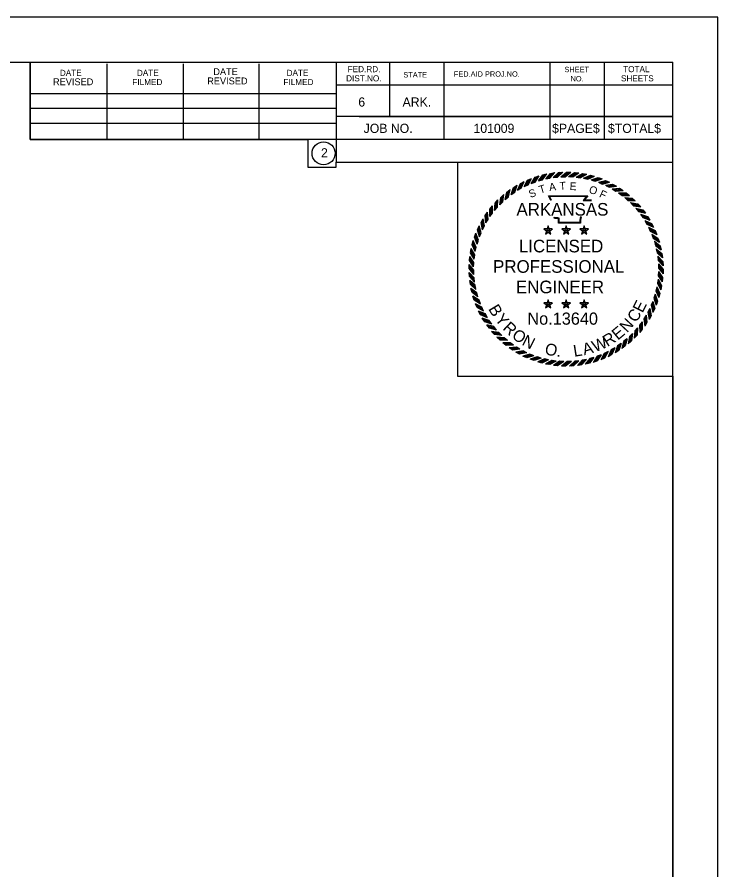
# Model space of a CAD drawing. Extents: x 0 to 1228740, y 0 to 152440.
# Drawn here: x 25.03 to 34, y 11.09 to 22 of the extents above; entities that cross this region are included whole.
import ezdxf

# ---------------------------------------------------------------- set-up
doc = ezdxf.new("R2010")
doc.units = 0
for name, color, linetype in [('R_Border', 7, 'Continuous'), ('R_No Plot', 7, 'Continuous'), ('STAMP', 7, 'Continuous')]:
    doc.layers.add(name, color=color, linetype=linetype)

msp = doc.modelspace()

# ---------------------------------------------------------------- linework, layer by layer
at = {"layer": 'R_Border'}
for p, q in [((1.516, 21.423), (33.423, 21.423)), ((25.197, 20.435), (25.197, 21.423)), ((26.183, 20.435), (26.183, 21.403)), ((27.159, 20.435), (27.159, 21.403)), ((28.127, 20.435), (28.127, 21.403)), ((29.113, 21.423), (29.113, 20.143)), ((29.797, 21.423), (29.797, 20.729)), ((30.491, 21.423), (30.491, 20.435)), ((31.849, 21.423), (31.849, 20.435)), ((32.543, 21.423), (32.543, 20.435)), ((33.423, 0.577), (33.423, 21.423)), ((33.423, 21.129), (29.113, 21.129)), ((33.423, 21.131), (33.423, 21.131)), ((25.197, 21.021), (29.113, 21.021)), ((25.197, 20.835), (29.113, 20.835)), ((33.423, 20.729), (29.113, 20.729)), ((29.409, 20.729), (33.423, 20.729)), ((25.197, 20.435), (25.197, 20.641)), ((25.197, 20.641), (29.113, 20.641)), ((33.423, 20.435), (25.197, 20.435)), ((29.113, 20.143), (33.423, 20.143))]:
    msp.add_line(p, q, dxfattribs=at)
msp.add_lwpolyline([(34, 22), (0, 22), (0, 0), (34, 0)], close=True, dxfattribs=at)
msp.add_circle((28.952, 20.257), 0.147, dxfattribs=at)
at = {"layer": 'R_No Plot'}
for points in [[(33.423, 17.405), (33.423, 10.871), (1.516, 10.871), (1.516, 21.423), (25.197, 21.423), (25.197, 20.435), (28.749, 20.435), (28.749, 20.078), (29.113, 20.078), (29.113, 20.143), (30.667, 20.143)], [(30.667, 20.143), (30.667, 17.405), (33.423, 17.405)]]:
    msp.add_lwpolyline(points, dxfattribs=at)
at = {"layer": 'STAMP'}
for p, q in [((31.66, 19.952), (31.711, 19.97)), ((31.758, 19.98), (31.811, 19.994)), ((31.858, 20.001), (31.912, 20.01)), ((31.96, 20.013), (32.014, 20.018)), ((32.063, 20.016), (32.118, 20.016)), ((32.165, 20.012), (32.219, 20.008)), ((32.267, 19.999), (32.321, 19.99)), ((32.367, 19.977), (32.42, 19.964)), ((31.471, 19.87), (31.519, 19.897)), ((31.564, 19.915), (31.613, 19.937)), ((31.609, 19.872), (31.66, 19.89)), ((31.701, 19.905), (31.754, 19.919)), ((31.795, 19.931), (31.849, 19.94)), ((31.892, 19.949), (31.946, 19.954)), ((31.989, 19.958), (32.044, 19.958)), ((32.087, 19.96), (32.141, 19.956)), ((32.184, 19.953), (32.238, 19.945)), ((32.281, 19.938), (32.334, 19.926)), ((32.376, 19.916), (32.428, 19.899)), ((32.465, 19.947), (32.517, 19.93)), ((32.469, 19.886), (32.52, 19.864)), ((32.56, 19.91), (32.61, 19.888)), ((32.652, 19.864), (32.7, 19.839)), ((31.299, 19.759), (31.342, 19.793)), ((31.353, 19.729), (31.399, 19.759)), ((31.383, 19.818), (31.428, 19.848)), ((31.435, 19.784), (31.482, 19.81)), ((31.52, 19.832), (31.57, 19.854)), ((32.56, 19.848), (32.608, 19.822)), ((32.646, 19.802), (32.692, 19.773)), ((32.729, 19.75), (32.772, 19.717)), ((32.74, 19.811), (32.786, 19.782)), ((32.823, 19.751), (32.867, 19.718)), ((31.148, 19.621), (31.184, 19.661)), ((31.206, 19.6), (31.246, 19.637)), ((31.221, 19.693), (31.26, 19.73)), ((31.277, 19.668), (31.32, 19.701)), ((32.807, 19.691), (32.848, 19.655)), ((32.901, 19.685), (32.942, 19.648)), ((31.081, 19.543), (31.114, 19.586)), ((31.141, 19.527), (31.178, 19.568)), ((32.88, 19.626), (32.918, 19.586)), ((32.948, 19.555), (32.982, 19.513)), ((32.973, 19.612), (33.011, 19.572)), ((33.039, 19.533), (33.073, 19.49)), ((30.968, 19.372), (30.994, 19.42)), ((31.021, 19.46), (31.051, 19.506)), ((31.082, 19.449), (31.115, 19.492)), ((33.009, 19.479), (33.039, 19.434)), ((33.098, 19.449), (33.129, 19.404)), ((30.923, 19.28), (30.944, 19.33)), ((30.985, 19.279), (31.01, 19.328)), ((31.03, 19.366), (31.059, 19.412)), ((31.826, 19.33), (31.791, 19.225)), ((31.859, 19.225), (31.826, 19.33)), ((32.056, 19.33), (32.022, 19.225)), ((32.09, 19.225), (32.056, 19.33)), ((32.287, 19.33), (32.253, 19.225)), ((32.321, 19.225), (32.287, 19.33)), ((33.064, 19.398), (33.09, 19.35)), ((33.112, 19.313), (33.134, 19.263)), ((33.15, 19.361), (33.177, 19.313)), ((30.885, 19.185), (30.902, 19.237)), ((30.947, 19.189), (30.968, 19.239)), ((31.88, 19.29), (31.771, 19.29)), ((31.771, 19.29), (31.859, 19.225)), ((31.792, 19.225), (31.881, 19.29)), ((31.818, 19.272), (31.834, 19.272)), ((31.826, 19.278), (31.826, 19.264)), ((32.111, 19.29), (32.001, 19.29)), ((32.001, 19.29), (32.09, 19.225)), ((32.022, 19.225), (32.111, 19.29)), ((32.048, 19.272), (32.065, 19.272)), ((32.056, 19.278), (32.056, 19.264)), ((32.342, 19.29), (32.232, 19.29)), ((32.232, 19.29), (32.321, 19.225)), ((32.253, 19.225), (32.342, 19.29)), ((32.279, 19.272), (32.295, 19.272)), ((32.287, 19.278), (32.287, 19.264)), ((33.152, 19.224), (33.171, 19.172)), ((33.195, 19.269), (33.217, 19.219)), ((30.855, 19.087), (30.868, 19.14)), ((30.917, 19.096), (30.934, 19.148)), ((33.186, 19.132), (33.199, 19.079)), ((33.232, 19.173), (33.25, 19.122)), ((30.834, 18.987), (30.842, 19.04)), ((30.894, 19.001), (30.907, 19.054)), ((33.211, 19.037), (33.221, 18.983)), ((33.26, 19.075), (33.274, 19.022)), ((30.821, 18.885), (30.825, 18.939)), ((30.879, 18.904), (30.888, 18.958)), ((33.229, 18.941), (33.234, 18.887)), ((33.281, 18.974), (33.29, 18.921)), ((30.816, 18.782), (30.815, 18.837)), ((30.873, 18.807), (30.877, 18.861)), ((33.238, 18.844), (33.239, 18.789)), ((33.293, 18.872), (33.298, 18.818)), ((33.297, 18.77), (33.297, 18.715)), ((30.82, 18.68), (30.815, 18.734)), ((30.874, 18.709), (30.874, 18.763)), ((30.884, 18.611), (30.879, 18.666)), ((33.24, 18.746), (33.236, 18.691)), ((33.292, 18.667), (33.288, 18.613)), ((30.832, 18.578), (30.822, 18.632)), ((30.902, 18.515), (30.892, 18.569)), ((33.219, 18.551), (33.206, 18.498)), ((33.233, 18.648), (33.225, 18.594)), ((33.279, 18.566), (33.27, 18.512)), ((30.852, 18.478), (30.838, 18.53)), ((30.927, 18.421), (30.913, 18.473)), ((33.196, 18.456), (33.179, 18.404)), ((33.257, 18.465), (33.244, 18.413)), ((30.881, 18.379), (30.863, 18.431)), ((30.918, 18.284), (30.895, 18.333)), ((30.96, 18.329), (30.942, 18.38)), ((31.88, 18.344), (31.771, 18.344)), ((31.771, 18.344), (31.859, 18.279)), ((31.826, 18.384), (31.791, 18.279)), ((31.792, 18.279), (31.881, 18.344)), ((31.859, 18.279), (31.826, 18.384)), ((31.826, 18.332), (31.826, 18.318)), ((32.111, 18.344), (32.001, 18.344)), ((32.001, 18.344), (32.09, 18.279)), ((32.056, 18.384), (32.022, 18.279)), ((32.022, 18.279), (32.111, 18.344)), ((32.09, 18.279), (32.056, 18.384)), ((32.056, 18.332), (32.056, 18.318)), ((32.342, 18.344), (32.232, 18.344)), ((32.232, 18.344), (32.321, 18.279)), ((32.287, 18.384), (32.253, 18.279)), ((32.253, 18.279), (32.342, 18.344)), ((32.321, 18.279), (32.287, 18.384)), ((32.287, 18.332), (32.287, 18.318)), ((33.166, 18.363), (33.144, 18.313)), ((33.228, 18.367), (33.21, 18.316)), ((30.962, 18.191), (30.936, 18.239)), ((31.001, 18.24), (30.979, 18.289)), ((31.818, 18.326), (31.834, 18.326)), ((32.048, 18.326), (32.065, 18.326)), ((32.279, 18.326), (32.295, 18.326)), ((33.128, 18.273), (33.102, 18.225)), ((33.19, 18.272), (33.168, 18.222)), ((31.014, 18.103), (30.984, 18.148)), ((31.049, 18.154), (31.023, 18.202)), ((31.104, 18.073), (31.073, 18.119)), ((33.083, 18.186), (33.053, 18.14)), ((33.144, 18.18), (33.119, 18.132)), ((31.074, 18.019), (31.04, 18.062)), ((31.165, 17.997), (31.131, 18.04)), ((32.972, 18.025), (32.935, 17.985)), ((33.03, 18.103), (32.997, 18.06)), ((33.031, 18.009), (32.998, 17.966)), ((33.091, 18.092), (33.062, 18.047)), ((31.139, 17.941), (31.102, 17.98)), ((31.212, 17.868), (31.171, 17.904)), ((31.232, 17.926), (31.195, 17.966)), ((31.305, 17.861), (31.265, 17.897)), ((32.906, 17.952), (32.867, 17.915)), ((32.965, 17.931), (32.928, 17.891)), ((31.289, 17.801), (31.246, 17.834)), ((31.384, 17.802), (31.34, 17.835)), ((32.759, 17.823), (32.714, 17.793)), ((32.813, 17.793), (32.771, 17.76)), ((32.835, 17.885), (32.793, 17.851)), ((32.892, 17.859), (32.852, 17.822)), ((31.373, 17.741), (31.327, 17.77)), ((31.46, 17.688), (31.412, 17.714)), ((31.466, 17.75), (31.42, 17.779)), ((31.553, 17.705), (31.505, 17.73)), ((31.643, 17.667), (31.593, 17.688)), ((32.504, 17.68), (32.452, 17.662)), ((32.593, 17.721), (32.543, 17.698)), ((32.641, 17.682), (32.594, 17.656)), ((32.678, 17.769), (32.63, 17.742)), ((32.73, 17.734), (32.684, 17.704)), ((31.552, 17.643), (31.502, 17.664)), ((31.648, 17.605), (31.596, 17.622)), ((31.736, 17.636), (31.685, 17.654)), ((31.746, 17.575), (31.693, 17.588)), ((31.831, 17.614), (31.779, 17.627)), ((31.928, 17.599), (31.874, 17.608)), ((32.026, 17.593), (31.972, 17.597)), ((32.124, 17.594), (32.069, 17.594)), ((32.221, 17.604), (32.167, 17.599)), ((32.317, 17.621), (32.264, 17.612)), ((32.355, 17.572), (32.302, 17.558)), ((32.412, 17.647), (32.359, 17.633)), ((32.453, 17.601), (32.402, 17.583)), ((32.549, 17.638), (32.499, 17.615)), ((31.846, 17.554), (31.792, 17.562)), ((31.948, 17.54), (31.893, 17.544)), ((32.05, 17.536), (31.996, 17.535)), ((32.152, 17.539), (32.098, 17.534)), ((32.254, 17.552), (32.201, 17.542))]:
    msp.add_line(p, q, dxfattribs=at)
for points in [[(31.643, 19.885), (31.694, 19.964)], [(31.66, 19.89), (31.711, 19.97)], [(31.701, 19.905), (31.758, 19.98)], [(31.718, 19.91), (31.775, 19.985)], [(31.736, 19.915), (31.793, 19.99)], [(31.754, 19.919), (31.811, 19.994)], [(31.795, 19.931), (31.858, 20.001)], [(31.813, 19.934), (31.876, 20.004)], [(31.831, 19.937), (31.894, 20.007)], [(31.849, 19.94), (31.912, 20.01)], [(31.892, 19.948), (31.96, 20.013)], [(31.909, 19.95), (31.978, 20.014)], [(31.928, 19.952), (31.996, 20.017)], [(31.946, 19.954), (32.014, 20.018)], [(31.989, 19.958), (32.063, 20.016)], [(32.006, 19.958), (32.081, 20.016)], [(32.025, 19.958), (32.1, 20.016)], [(32.043, 19.958), (32.118, 20.016)], [(32.087, 19.96), (32.165, 20.012)], [(32.104, 19.958), (32.182, 20.01)], [(32.123, 19.957), (32.201, 20.009)], [(32.141, 19.956), (32.219, 20.008)], [(32.184, 19.953), (32.267, 19.999)], [(32.202, 19.95), (32.284, 19.996)], [(32.22, 19.948), (32.303, 19.993)], [(32.238, 19.945), (32.321, 19.99)], [(32.281, 19.938), (32.367, 19.977)], [(32.298, 19.934), (32.384, 19.973)], [(32.317, 19.93), (32.402, 19.969)], [(32.334, 19.926), (32.42, 19.964)], [(31.435, 19.784), (31.471, 19.87)], [(31.45, 19.792), (31.487, 19.878)], [(31.466, 19.801), (31.503, 19.888)], [(31.482, 19.81), (31.519, 19.897)], [(31.52, 19.831), (31.564, 19.915)], [(31.536, 19.838), (31.58, 19.922)], [(31.553, 19.847), (31.597, 19.93)], [(31.57, 19.854), (31.613, 19.937)], [(31.609, 19.872), (31.659, 19.951)], [(31.625, 19.878), (31.676, 19.957)], [(32.376, 19.916), (32.465, 19.947)], [(32.393, 19.91), (32.482, 19.942)], [(32.411, 19.905), (32.5, 19.936)], [(32.428, 19.899), (32.517, 19.93)], [(32.469, 19.886), (32.56, 19.91)], [(32.485, 19.879), (32.576, 19.903)], [(32.503, 19.872), (32.594, 19.896)], [(32.52, 19.864), (32.611, 19.888)], [(32.56, 19.848), (32.652, 19.864)], [(32.575, 19.839), (32.668, 19.856)], [(31.277, 19.667), (31.299, 19.759)], [(31.291, 19.678), (31.313, 19.77)], [(31.306, 19.69), (31.328, 19.782)], [(31.32, 19.701), (31.342, 19.793)], [(31.353, 19.729), (31.383, 19.818)], [(31.368, 19.738), (31.398, 19.828)], [(31.384, 19.749), (31.413, 19.838)], [(31.399, 19.759), (31.428, 19.848)], [(32.592, 19.831), (32.685, 19.847)], [(32.608, 19.822), (32.7, 19.839)], [(32.646, 19.802), (32.74, 19.811)], [(32.661, 19.793), (32.755, 19.802)], [(32.677, 19.783), (32.771, 19.792)], [(32.692, 19.773), (32.786, 19.782)], [(32.729, 19.75), (32.823, 19.751)], [(31.165, 19.554), (31.172, 19.648)], [(31.178, 19.568), (31.184, 19.661)], [(31.206, 19.6), (31.221, 19.693)], [(31.219, 19.612), (31.234, 19.705)], [(31.233, 19.625), (31.247, 19.718)], [(31.246, 19.637), (31.26, 19.73)], [(31.861, 19.652), (31.832, 19.715), (32.333, 19.715), (32.291, 19.662), (32.325, 19.663), (32.354, 19.663), (32.382, 19.66)], [(31.868, 19.655), (31.844, 19.707), (32.317, 19.707), (32.275, 19.654), (32.325, 19.655), (32.353, 19.655), (32.381, 19.652)], [(32.743, 19.74), (32.837, 19.74)], [(32.758, 19.728), (32.852, 19.729)], [(32.772, 19.717), (32.867, 19.718)], [(32.807, 19.691), (32.901, 19.685)], [(32.82, 19.68), (32.914, 19.673)], [(32.834, 19.667), (32.928, 19.66)], [(32.848, 19.655), (32.942, 19.648)], [(31.082, 19.449), (31.081, 19.543)], [(31.093, 19.463), (31.092, 19.557)], [(31.104, 19.478), (31.103, 19.572)], [(31.115, 19.492), (31.114, 19.586)], [(31.141, 19.527), (31.148, 19.621)], [(31.153, 19.54), (31.16, 19.634)], [(32.88, 19.626), (32.973, 19.612)], [(32.892, 19.613), (32.985, 19.599)], [(32.905, 19.6), (32.998, 19.585)], [(32.918, 19.587), (33.011, 19.572)], [(32.948, 19.555), (33.039, 19.533)], [(32.958, 19.541), (33.05, 19.519)], [(31.01, 19.328), (30.994, 19.42)], [(31.03, 19.366), (31.021, 19.46)], [(31.04, 19.381), (31.031, 19.475)], [(31.049, 19.397), (31.041, 19.491)], [(31.059, 19.412), (31.051, 19.506)], [(32.254, 19.442), (32.246, 19.435), (32.243, 19.424), (32.24, 19.398), (32.24, 19.364), (31.96, 19.364), (31.96, 19.411), (31.96, 19.421), (31.949, 19.424), (31.909, 19.424), (31.902, 19.435)], [(32.249, 19.448), (32.239, 19.439), (32.235, 19.426), (32.232, 19.399), (32.232, 19.372), (31.968, 19.372), (31.968, 19.411), (31.968, 19.427), (31.95, 19.432), (31.913, 19.432), (31.908, 19.44)], [(32.97, 19.527), (33.062, 19.505)], [(32.982, 19.513), (33.073, 19.49)], [(33.009, 19.479), (33.098, 19.449)], [(33.019, 19.464), (33.108, 19.435)], [(33.029, 19.449), (33.119, 19.419)], [(33.039, 19.434), (33.129, 19.404)], [(30.961, 19.223), (30.937, 19.314)], [(30.968, 19.239), (30.944, 19.33)], [(30.985, 19.279), (30.968, 19.372)], [(30.993, 19.295), (30.977, 19.387)], [(31.002, 19.312), (30.985, 19.404)], [(33.064, 19.398), (33.15, 19.361)], [(33.072, 19.383), (33.159, 19.346)], [(33.082, 19.366), (33.168, 19.329)], [(33.09, 19.35), (33.177, 19.313)], [(33.112, 19.313), (33.195, 19.269)], [(30.922, 19.113), (30.891, 19.201)], [(30.928, 19.131), (30.896, 19.219)], [(30.934, 19.148), (30.902, 19.237)], [(30.947, 19.189), (30.923, 19.28)], [(30.954, 19.205), (30.93, 19.296)], [(33.119, 19.297), (33.202, 19.253)], [(33.127, 19.28), (33.21, 19.236)], [(33.134, 19.263), (33.217, 19.219)], [(33.152, 19.224), (33.232, 19.173)], [(33.158, 19.207), (33.237, 19.156)], [(30.898, 19.018), (30.86, 19.104)], [(30.902, 19.036), (30.864, 19.122)], [(30.907, 19.054), (30.868, 19.14)], [(30.917, 19.096), (30.885, 19.185)], [(33.165, 19.189), (33.244, 19.139)], [(33.171, 19.172), (33.25, 19.122)], [(33.186, 19.132), (33.26, 19.075)], [(33.19, 19.115), (33.265, 19.058)], [(33.195, 19.097), (33.27, 19.039)], [(30.879, 18.904), (30.834, 18.986)], [(30.882, 18.921), (30.837, 19.004)], [(30.885, 18.94), (30.839, 19.022)], [(30.888, 18.958), (30.842, 19.04)], [(30.894, 19.001), (30.855, 19.087)], [(33.2, 19.079), (33.274, 19.022)], [(33.211, 19.037), (33.281, 18.974)], [(33.214, 19.02), (33.284, 18.957)], [(33.218, 19.001), (33.288, 18.938)], [(33.221, 18.984), (33.29, 18.92)], [(30.873, 18.807), (30.821, 18.885)], [(30.874, 18.824), (30.822, 18.902)], [(30.875, 18.843), (30.823, 18.921)], [(30.877, 18.861), (30.825, 18.939)], [(33.229, 18.941), (33.293, 18.872)], [(33.23, 18.924), (33.295, 18.855)], [(33.232, 18.905), (33.297, 18.836)], [(33.234, 18.887), (33.298, 18.818)], [(30.874, 18.763), (30.815, 18.837)], [(30.874, 18.745), (30.815, 18.819)], [(30.874, 18.726), (30.816, 18.8)], [(30.874, 18.709), (30.816, 18.782)], [(33.238, 18.844), (33.297, 18.77)], [(33.238, 18.826), (33.297, 18.752)], [(33.239, 18.807), (33.297, 18.734)], [(33.239, 18.789), (33.297, 18.715)], [(30.879, 18.666), (30.815, 18.734)], [(30.88, 18.648), (30.816, 18.716)], [(30.883, 18.629), (30.818, 18.697)], [(30.884, 18.611), (30.82, 18.68)], [(33.236, 18.691), (33.288, 18.613)], [(33.237, 18.709), (33.29, 18.631)], [(33.238, 18.728), (33.291, 18.65)], [(33.24, 18.746), (33.292, 18.667)], [(30.892, 18.569), (30.822, 18.632)], [(30.895, 18.551), (30.825, 18.614)], [(30.899, 18.532), (30.829, 18.595)], [(30.902, 18.515), (30.832, 18.578)], [(33.219, 18.551), (33.257, 18.466)], [(33.225, 18.594), (33.27, 18.512)], [(33.228, 18.612), (33.273, 18.53)], [(33.23, 18.631), (33.276, 18.549)], [(33.233, 18.648), (33.279, 18.566)], [(30.913, 18.473), (30.838, 18.53)], [(30.918, 18.456), (30.843, 18.513)], [(30.923, 18.438), (30.848, 18.495)], [(30.927, 18.421), (30.852, 18.478)], [(33.19, 18.44), (33.222, 18.351)], [(33.196, 18.456), (33.228, 18.367)], [(33.206, 18.498), (33.245, 18.413)], [(33.21, 18.516), (33.249, 18.43)], [(33.214, 18.534), (33.253, 18.449)], [(30.942, 18.38), (30.863, 18.431)], [(30.948, 18.363), (30.869, 18.414)], [(30.955, 18.345), (30.875, 18.396)], [(30.96, 18.329), (30.881, 18.379)], [(30.979, 18.289), (30.895, 18.333)], [(33.152, 18.33), (33.176, 18.239)], [(33.159, 18.347), (33.183, 18.256)], [(33.166, 18.363), (33.19, 18.272)], [(33.179, 18.404), (33.21, 18.316)], [(33.185, 18.422), (33.216, 18.333)], [(30.986, 18.273), (30.903, 18.317)], [(30.994, 18.256), (30.911, 18.3)], [(31.001, 18.24), (30.918, 18.284)], [(31.023, 18.202), (30.936, 18.239)], [(31.031, 18.186), (30.945, 18.223)], [(33.102, 18.225), (33.119, 18.132)], [(33.111, 18.241), (33.128, 18.148)], [(33.12, 18.258), (33.136, 18.165)], [(33.128, 18.273), (33.144, 18.18)], [(33.144, 18.313), (33.168, 18.222)], [(31.041, 18.17), (30.954, 18.207)], [(31.049, 18.154), (30.962, 18.191)], [(31.073, 18.119), (30.984, 18.148)], [(31.083, 18.103), (30.994, 18.133)], [(31.094, 18.088), (31.005, 18.118)], [(33.053, 18.14), (33.062, 18.046)], [(33.063, 18.155), (33.072, 18.062)], [(33.073, 18.171), (33.082, 18.078)], [(33.083, 18.186), (33.091, 18.092)], [(31.104, 18.073), (31.014, 18.103)], [(31.131, 18.04), (31.04, 18.062)], [(31.142, 18.025), (31.051, 18.048)], [(31.154, 18.011), (31.063, 18.033)], [(31.165, 17.997), (31.074, 18.019)], [(32.96, 18.012), (32.953, 17.919)], [(32.972, 18.025), (32.965, 17.931)], [(32.997, 18.06), (32.998, 17.966)], [(33.009, 18.074), (33.01, 17.98)], [(33.02, 18.09), (33.021, 17.995)], [(33.03, 18.103), (33.031, 18.009)], [(31.195, 17.966), (31.102, 17.98)], [(31.207, 17.952), (31.114, 17.967)], [(31.221, 17.939), (31.128, 17.953)], [(31.232, 17.926), (31.139, 17.941)], [(31.265, 17.897), (31.171, 17.904)], [(31.278, 17.885), (31.184, 17.892)], [(32.867, 17.915), (32.852, 17.822)], [(32.88, 17.927), (32.866, 17.834)], [(32.894, 17.94), (32.879, 17.847)], [(32.906, 17.952), (32.892, 17.859)], [(32.935, 17.985), (32.928, 17.891)], [(32.947, 17.998), (32.941, 17.904)], [(31.293, 17.873), (31.199, 17.88)], [(31.305, 17.861), (31.212, 17.868)], [(31.34, 17.835), (31.246, 17.834)], [(31.355, 17.824), (31.26, 17.823)], [(31.37, 17.813), (31.276, 17.812)], [(31.384, 17.802), (31.289, 17.801)], [(32.714, 17.793), (32.684, 17.704)], [(32.729, 17.803), (32.699, 17.714)], [(32.745, 17.814), (32.715, 17.725)], [(32.759, 17.824), (32.73, 17.734)], [(32.793, 17.851), (32.771, 17.759)], [(32.807, 17.862), (32.785, 17.771)], [(32.822, 17.874), (32.8, 17.783)], [(32.836, 17.885), (32.813, 17.793)], [(31.42, 17.779), (31.327, 17.77)], [(31.436, 17.769), (31.342, 17.761)], [(31.452, 17.759), (31.358, 17.751)], [(31.466, 17.75), (31.373, 17.741)], [(31.505, 17.73), (31.412, 17.714)], [(31.521, 17.721), (31.428, 17.705)], [(31.538, 17.713), (31.445, 17.696)], [(31.553, 17.705), (31.46, 17.688)], [(31.593, 17.688), (31.502, 17.664)], [(31.61, 17.681), (31.519, 17.657)], [(31.627, 17.674), (31.536, 17.65)], [(32.487, 17.674), (32.437, 17.595)], [(32.504, 17.68), (32.453, 17.601)], [(32.543, 17.698), (32.499, 17.615)], [(32.56, 17.706), (32.516, 17.622)], [(32.577, 17.714), (32.533, 17.631)], [(32.593, 17.721), (32.549, 17.638)], [(32.631, 17.742), (32.594, 17.656)], [(32.646, 17.751), (32.61, 17.664)], [(32.663, 17.76), (32.626, 17.674)], [(32.678, 17.769), (32.641, 17.682)], [(31.643, 17.667), (31.552, 17.643)], [(31.685, 17.654), (31.596, 17.622)], [(31.702, 17.648), (31.613, 17.616)], [(31.72, 17.642), (31.631, 17.611)], [(31.736, 17.636), (31.648, 17.605)], [(31.779, 17.627), (31.693, 17.588)], [(31.796, 17.622), (31.71, 17.584)], [(31.815, 17.618), (31.729, 17.579)], [(31.832, 17.614), (31.746, 17.575)], [(31.874, 17.608), (31.792, 17.562)], [(31.892, 17.605), (31.81, 17.559)], [(31.911, 17.602), (31.829, 17.557)], [(31.928, 17.599), (31.846, 17.554)], [(31.972, 17.597), (31.893, 17.544)], [(31.99, 17.595), (31.911, 17.543)], [(32.008, 17.594), (31.93, 17.542)], [(32.026, 17.593), (31.948, 17.54)], [(32.069, 17.594), (31.996, 17.535)], [(32.087, 17.594), (32.014, 17.535)], [(32.106, 17.594), (32.033, 17.536)], [(32.124, 17.594), (32.05, 17.536)], [(32.167, 17.599), (32.098, 17.534)], [(32.185, 17.6), (32.116, 17.536)], [(32.204, 17.602), (32.135, 17.538)], [(32.221, 17.604), (32.153, 17.539)], [(32.264, 17.612), (32.201, 17.542)], [(32.282, 17.615), (32.219, 17.545)], [(32.3, 17.619), (32.237, 17.549)], [(32.317, 17.621), (32.254, 17.552)], [(32.359, 17.633), (32.302, 17.558)], [(32.377, 17.637), (32.32, 17.563)], [(32.395, 17.643), (32.338, 17.568)], [(32.412, 17.647), (32.355, 17.572)], [(32.453, 17.662), (32.402, 17.583)], [(32.47, 17.668), (32.419, 17.588)]]:
    msp.add_lwpolyline(points, dxfattribs=at)

# ---------------------------------------------------------------- texts
at = {"layer": 'R_Border'}
for s, height, p in [('DATE', 0.0782, (25.577, 21.247)), ('DATE', 0.0782, (26.563, 21.247)), ('DATE', 0.0879, (27.541, 21.257)), ('DATE', 0.0782, (28.479, 21.247)), ('FED.RD.', 0.0782, (29.261, 21.295)), ('STATE', 0.0684, (29.973, 21.227)), ('FED.AID PROJ.NO.', 0.0684, (30.619, 21.237)), ('SHEET', 0.0684, (32.035, 21.295)), ('TOTAL', 0.0782, (32.787, 21.295)), ('REVISED', 0.0879, (25.489, 21.128)), ('FILMED', 0.0782, (26.505, 21.129)), ('REVISED', 0.0879, (27.463, 21.139)), ('FILMED', 0.0782, (28.439, 21.129)), ('DIST.NO.', 0.0782, (29.241, 21.177)), ('NO.', 0.0684, (32.113, 21.177)), ('SHEETS', 0.0782, (32.759, 21.177)), ('6', 0.117, (29.397, 20.855)), ('ARK.', 0.1172, (29.963, 20.855)), ('JOB NO.', 0.1172, (29.465, 20.518)), ('101009', 0.1172, (30.871, 20.518)), ('$PAGE$', 0.1172, (31.877, 20.518)), ('$TOTAL$', 0.1172, (32.592, 20.518)), ('2', 0.117, (28.919, 20.205))]:
    msp.add_text(s, height=height, dxfattribs=at).set_placement(p)
at = {"layer": 'STAMP'}
for s, height, rotation, p in [('T', 0.099, 16.9015, (31.725, 19.741)), ('A', 0.099, 8.6788, (31.845, 19.773)), ('T', 0.099, 1.4789, (31.973, 19.792)), ('E', 0.099, 356.672, (32.1, 19.789)), ('S', 0.099, 19.7726, (31.599, 19.685)), ('O', 0.099, 341.2218, (32.34, 19.755)), ('F', 0.099, 335.3628, (32.473, 19.703)), ('B', 0.15, 300.7985, (31.056, 18.268)), ('E', 0.15, 63.7362, (33.035, 18.208)), ('Y', 0.15, 308.8241, (31.137, 18.133)), ('C', 0.15, 56.0754, (32.95, 18.083)), ('N', 0.15, 47.3202, (32.835, 17.956)), ('R', 0.15, 316.8497, (31.235, 18.01)), ('O', 0.15, 324.8753, (31.351, 17.902)), ('E', 0.15, 39.6594, (32.718, 17.86)), ('N', 0.15, 332.9009, (31.48, 17.811)), ('W', 0.15, 22.8786, (32.426, 17.71)), ('R', 0.15, 31.6338, (32.584, 17.778)), ('O', 0.15, 349.3169, (31.776, 17.686)), ('L', 0.15, 9.0162, (32.16, 17.654)), ('A', 0.15, 15.5826, (32.288, 17.672)), ('.', 0.15, 357.3425, (31.931, 17.657))]:
    msp.add_text(s, height=height, rotation=rotation, dxfattribs=at).set_placement(p)
for s, height, p in [('ARKANSAS', 0.1615, (31.421, 19.46)), ('LICENSED', 0.1615, (31.452, 18.99)), ('PROFESSIONAL', 0.1615, (31.122, 18.729)), ('ENGINEER', 0.1615, (31.414, 18.467)), ('No.13640', 0.1557, (31.561, 18.065))]:
    msp.add_text(s, height=height, dxfattribs=at).set_placement(p)

doc.saveas('drawing.dxf')
